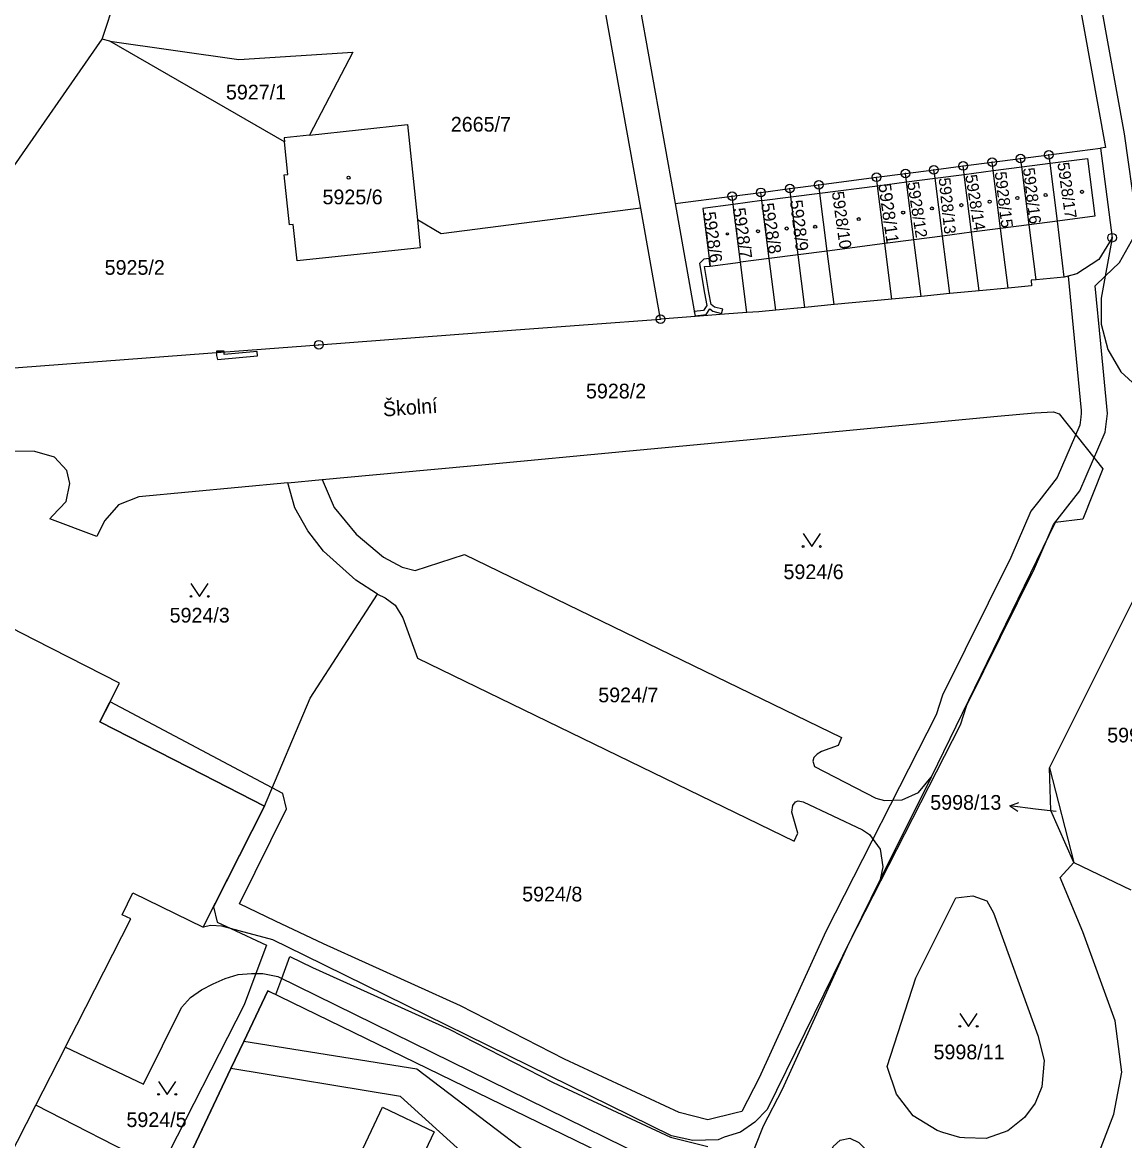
# Model space of a CAD drawing. Extents: x -644096 to -634268, y -1141430 to -1133463.
# Drawn here: x -639819.5 to -639692.1, y -1138952.5 to -1138823.3 of the extents above; entities that cross this region are included whole.
import ezdxf

# ---------------------------------------------------------------- set-up
doc = ezdxf.new("R2010")
doc.units = 0
for name, color, linetype in [('_CIVIL_CONSTRUCTION', 7, 'Continuous'), ('B_Hranice _3D', 7, 'Continuous'), ('M_Svah_Nasyp', 7, 'Continuous'), ('M_Svah_Zarez', 7, 'Continuous'), ('svrsek_osa_sjezdy', 7, 'Continuous'), ('svrsek_osa_terminal_VRT', 7, 'Continuous'), ('svrsek_osa_VRT', 7, 'Continuous'), ('svrsek_popisy_VRT', 7, 'Continuous'), ('terminal_VRT', 7, 'Continuous')]:
    doc.layers.add(name, color=color, linetype=linetype)

msp = doc.modelspace()

# ---------------------------------------------------------------- linework, layer by layer
at = {"layer": '_CIVIL_CONSTRUCTION'}
for centre, radius in [((-639700.83, -1138838.58), 0.5), ((-639710.73, -1138839.87), 0.5), ((-639707.38, -1138839.43), 0.5), ((-639707.38, -1138839.43), 0.0303), ((-639704.1, -1138839), 0.5), ((-639704.1, -1138839), 0.0303), ((-639700.83, -1138838.58), 0.0303), ((-639720.76, -1138841.18), 0.5), ((-639717.4, -1138840.74), 0.5), ((-639717.4, -1138840.74), 0.0303), ((-639714.11, -1138840.31), 0.5), ((-639714.11, -1138840.31), 0.0303), ((-639710.73, -1138839.87), 0.0303), ((-639730.78, -1138842.48), 0.5), ((-639727.41, -1138842.04), 0.5), ((-639727.41, -1138842.04), 0.0303), ((-639720.76, -1138841.18), 0.0303), ((-639737.44, -1138843.35), 0.5), ((-639737.44, -1138843.35), 0.0303), ((-639734.13, -1138842.92), 0.5), ((-639734.13, -1138842.92), 0.0303), ((-639730.78, -1138842.48), 0.0303), ((-639693.53, -1138848.16), 0.5), ((-639693.53, -1138848.16), 0.0303), ((-639745.7, -1138857.57), 0.5), ((-639745.7, -1138857.57), 0.0303), ((-639785.19, -1138860.53), 0.5), ((-639785.19, -1138860.53), 0.0303)]:
    msp.add_circle(centre, radius, dxfattribs=at)
at = {"layer": 'B_Hranice _3D'}
for points in [[(-639710.19, -1138704.51), (-639707.75, -1138718.55), (-639706.98, -1138722.49), (-639707.1, -1138723), (-639703.72, -1138740.51), (-639711.6, -1138742.31), (-639704.99, -1138778.75), (-639703.51, -1138786.84), (-639694.29, -1138837.72), (-639694.86, -1138837.8), (-639693.53, -1138848.16), (-639695.07, -1138850.69), (-639697.61, -1138852.33), (-639698.6, -1138852.6), (-639697.11, -1138868.12)], [(-639737.91, -1138961.12), (-639733.8, -1138950.84), (-639731.61, -1138946.6), (-639723.9, -1138929.67), (-639711.06, -1138904.49), (-639710.31, -1138902.21), (-639702.5, -1138886.39), (-639700.31, -1138881.33), (-639697.27, -1138877.43), (-639694.34, -1138870.64), (-639694.06, -1138868.48), (-639694.83, -1138860.43), (-639695.48, -1138853.71), (-639694.32, -1138852.6), (-639692.67, -1138851.01), (-639690.94, -1138847.96), (-639690.76, -1138845.7), (-639692.1, -1138836.17), (-639698.53, -1138800.59)], [(-639697.11, -1138868.12), (-639697.08, -1138868.44), (-639697.14, -1138868.91), (-639697.26, -1138869.84), (-639699.87, -1138875.89), (-639702, -1138878.63), (-639702.91, -1138879.79), (-639705.23, -1138885.13), (-639713.12, -1138901.05), (-639713.84, -1138903.33), (-639726.6, -1138928.37), (-639734.31, -1138945.28), (-639736.32, -1138949.18), (-639736.97, -1138949.34), (-639740.23, -1138950.14), (-639743.57, -1138949.3), (-639756.81, -1138943.14), (-639768.83, -1138936.97), (-639784.68, -1138929.79), (-639790.2, -1138927.17), (-639794.36, -1138925.18), (-639788.95, -1138914.19), (-639789.37, -1138912.41), (-639809.33, -1138901.81), (-639810.5, -1138904.13), (-639798.6, -1138910.23), (-639791.48, -1138913.88), (-639797.39, -1138925.51), (-639796.96, -1138927.29), (-639795.38, -1138928.02), (-639791.24, -1138929.93), (-639792.48, -1138933.22), (-639793.84, -1138936.84), (-639803.5, -1138955.81)], [(-639801.37, -1138956.9), (-639795.36, -1138944.2), (-639793.88, -1138941.09), (-639791.09, -1138935.21), (-639790.19, -1138935.65), (-639789.49, -1138933.8), (-639788.54, -1138931.27), (-639785.95, -1138932.51), (-639770.15, -1138939.67), (-639758.13, -1138945.84), (-639744.57, -1138952.14), (-639740.25, -1138953.22)]]:
    msp.add_lwpolyline(points, dxfattribs=at)
for points in [[(-639741.72, -1138857.2), (-639740.45, -1138857.04), (-639740.02, -1138856.4), (-639739.68, -1138856.67), (-639738.65, -1138856.92), (-639738.53, -1138856.44), (-639739.46, -1138856.21), (-639739.85, -1138855.9), (-639740.14, -1138854.49), (-639740.62, -1138851.51), (-639739.97, -1138851.46), (-639740.08, -1138850.56), (-639740.69, -1138850.63), (-639741.19, -1138851.14), (-639740.64, -1138854.59), (-639740.35, -1138855.99), (-639740.73, -1138856.58), (-639741.81, -1138856.71)], [(-639797.02, -1138861.27), (-639797.02, -1138861.42), (-639796.14, -1138861.36), (-639796.14, -1138861.27)], [(-639797.02, -1138861.42), (-639797.02, -1138861.77), (-639796.91, -1138862.23), (-639792.29, -1138861.83), (-639792.33, -1138861.33), (-639796.14, -1138861.67), (-639796.14, -1138861.36)]]:
    msp.add_lwpolyline(points, close=True, dxfattribs=at)
at = {"layer": 'M_Svah_Nasyp'}
for p, q in [((-639700.7, -1138839.55), (-639696.38, -1138838.99)), ((-639696.38, -1138838.99), (-639695.52, -1138845.68)), ((-639710.61, -1138840.84), (-639707.26, -1138840.41)), ((-639707.26, -1138840.41), (-639703.97, -1138839.98)), ((-639703.97, -1138839.98), (-639700.7, -1138839.55)), ((-639720.64, -1138842.15), (-639717.28, -1138841.71)), ((-639717.28, -1138841.71), (-639713.99, -1138841.28)), ((-639713.99, -1138841.28), (-639710.61, -1138840.84)), ((-639730.66, -1138843.45), (-639727.29, -1138843.01)), ((-639727.29, -1138843.01), (-639720.64, -1138842.15)), ((-639737.32, -1138844.31), (-639740.82, -1138844.77)), ((-639734.01, -1138843.88), (-639737.32, -1138844.31)), ((-639734.01, -1138843.88), (-639730.66, -1138843.45)), ((-639740.82, -1138844.77), (-639739.97, -1138851.46)), ((-639695.52, -1138845.68), (-639699.84, -1138846.24)), ((-639706.41, -1138847.1), (-639709.76, -1138847.53)), ((-639703.11, -1138846.67), (-639706.41, -1138847.1)), ((-639699.84, -1138846.24), (-639703.11, -1138846.67)), ((-639716.43, -1138848.4), (-639719.79, -1138848.84)), ((-639713.14, -1138847.97), (-639716.43, -1138848.4)), ((-639709.76, -1138847.53), (-639713.14, -1138847.97)), ((-639726.44, -1138849.7), (-639729.81, -1138850.14)), ((-639719.79, -1138848.84), (-639726.44, -1138849.7)), ((-639739.97, -1138851.46), (-639736.47, -1138851)), ((-639733.16, -1138850.57), (-639736.47, -1138851)), ((-639729.81, -1138850.14), (-639733.16, -1138850.57))]:
    msp.add_line(p, q, dxfattribs=at)
at = {"layer": 'M_Svah_Zarez'}
for centre, radius in [((-639781.77, -1138841.23), 0.175), ((-639701.21, -1138843.23), 0.175), ((-639697, -1138842.86), 0.175), ((-639714.35, -1138844.78), 0.175), ((-639710.94, -1138844.4), 0.175), ((-639707.68, -1138844), 0.175), ((-639704.47, -1138843.57), 0.175), ((-639722.8, -1138846.01), 0.175), ((-639717.67, -1138845.26), 0.175), ((-639734.45, -1138847.41), 0.175), ((-639731.13, -1138847.1), 0.175), ((-639727.84, -1138846.9), 0.175), ((-639737.99, -1138847.73), 0.117)]:
    msp.add_circle(centre, radius, dxfattribs=at)
at = {"layer": 'svrsek_osa_sjezdy'}
for points in [[(-639729.24, -1138882.36), (-639728.24, -1138883.86), (-639727.24, -1138882.36)], [(-639799.98, -1138888.13), (-639798.98, -1138889.63), (-639797.98, -1138888.13)], [(-639711.12, -1138937.83), (-639710.12, -1138939.33), (-639709.12, -1138937.83)], [(-639803.73, -1138945.69), (-639802.73, -1138947.19), (-639801.73, -1138945.69)]]:
    msp.add_lwpolyline(points, dxfattribs=at)
for centre in [(-639729.24, -1138883.86), (-639727.24, -1138883.86), (-639799.98, -1138889.63), (-639797.98, -1138889.63), (-639711.12, -1138939.33), (-639709.12, -1138939.33), (-639803.73, -1138947.19), (-639801.73, -1138947.19)]:
    msp.add_circle(centre, 0.1, dxfattribs=at)
at = {"layer": 'svrsek_osa_terminal_VRT'}
msp.add_arc((-642050.26, -1145189.6), 8802.25, 41.413152, 75.317049, dxfattribs=at)
at = {"layer": 'svrsek_popisy_VRT'}
for p, q in [((-639705.35, -1138913.84), (-639704.29, -1138913.47)), ((-639702.37, -1138914.21), (-639705.35, -1138913.84)), ((-639705.35, -1138913.84), (-639704.42, -1138914.46)), ((-639699.97, -1138914.49), (-639702.37, -1138914.21))]:
    msp.add_line(p, q, dxfattribs=at)
at = {"layer": 'terminal_VRT'}
for p, q in [((-639753.15, -1138793.2), (-639744.04, -1138844.21)), ((-639810.25, -1138825.23), (-639808.3, -1138819.29)), ((-639821.39, -1138841.23), (-639810.25, -1138825.23)), ((-639809.36, -1138825.44), (-639810.25, -1138825.23)), ((-639789.17, -1138837.08), (-639809.36, -1138825.44)), ((-639700.83, -1138838.58), (-639694.86, -1138837.8)), ((-639694.86, -1138837.8), (-639693.53, -1138848.16)), ((-639710.73, -1138839.87), (-639707.38, -1138839.43)), ((-639707.38, -1138839.43), (-639704.1, -1138839)), ((-639704.1, -1138839), (-639700.83, -1138838.58)), ((-639720.76, -1138841.18), (-639717.4, -1138840.74)), ((-639717.4, -1138840.74), (-639714.11, -1138840.31)), ((-639714.11, -1138840.31), (-639710.73, -1138839.87)), ((-639730.78, -1138842.48), (-639727.41, -1138842.04)), ((-639727.41, -1138842.04), (-639720.76, -1138841.18)), ((-639744.04, -1138844.21), (-639737.44, -1138843.35)), ((-639737.44, -1138843.35), (-639734.13, -1138842.92)), ((-639734.13, -1138842.92), (-639730.78, -1138842.48)), ((-639744.04, -1138844.21), (-639741.71, -1138857.27)), ((-639745.7, -1138857.57), (-639748, -1138844.73)), ((-639699.05, -1138852.72), (-639702.29, -1138853.02)), ((-639715.6, -1138854.95), (-639718.97, -1138855.27)), ((-639712.29, -1138854.63), (-639715.6, -1138854.95)), ((-639708.9, -1138854.31), (-639712.29, -1138854.63)), ((-639705.53, -1138853.99), (-639708.9, -1138854.31)), ((-639729.04, -1138856.22), (-639732.4, -1138856.54)), ((-639725.65, -1138855.9), (-639729.04, -1138856.22)), ((-639718.97, -1138855.27), (-639725.65, -1138855.9)), ((-639741.71, -1138857.27), (-639745.7, -1138857.57)), ((-639788.77, -1138876.5), (-639784.81, -1138876.13)), ((-639714.43, -1138910.53), (-639720.34, -1138922.37)), ((-639700.74, -1138909.46), (-639697.94, -1138920.38)), ((-639798.59, -1138927.88), (-639791.48, -1138913.88)), ((-639697.94, -1138920.38), (-639691.37, -1138923.56)), ((-639793.88, -1138941.09), (-639795.36, -1138944.2)), ((-639817.92, -1138948.43), (-639814.49, -1138941.73)), ((-639795.36, -1138944.2), (-639801.37, -1138956.9)), ((-639801.37, -1138956.9), (-639817.92, -1138948.43))]:
    msp.add_line(p, q, dxfattribs=at)
for points in [[(-639704.99, -1138778.75), (-639703.51, -1138786.84), (-639694.29, -1138837.72), (-639694.86, -1138837.8)], [(-639748, -1138844.73), (-639752.48, -1138819.72), (-639755.46, -1138819.2)], [(-639809.36, -1138825.44), (-639794.44, -1138827.58), (-639781.26, -1138826.73), (-639786.27, -1138836.3)], [(-639786.27, -1138836.3), (-639774.96, -1138835.07), (-639773.81, -1138846.1)], [(-639786.27, -1138836.3), (-639789.22, -1138836.62), (-639789.17, -1138837.08)], [(-639773.81, -1138846.1), (-639773.48, -1138849.32), (-639787.72, -1138850.83), (-639788.18, -1138846.63), (-639788.6, -1138846.66), (-639789.21, -1138840.89), (-639788.77, -1138840.87), (-639789.17, -1138837.08)], [(-639705.53, -1138853.99), (-639706.41, -1138847.1), (-639707.26, -1138840.41), (-639707.38, -1138839.43)], [(-639702.29, -1138853.02), (-639703.11, -1138846.67), (-639703.97, -1138839.98), (-639704.1, -1138839)], [(-639699.05, -1138852.72), (-639699.84, -1138846.24), (-639700.7, -1138839.55), (-639700.83, -1138838.58)], [(-639715.6, -1138854.95), (-639716.43, -1138848.4), (-639717.28, -1138841.71), (-639717.4, -1138840.74)], [(-639712.29, -1138854.63), (-639713.14, -1138847.97), (-639713.99, -1138841.28), (-639714.11, -1138840.31)], [(-639708.9, -1138854.31), (-639709.76, -1138847.53), (-639710.61, -1138840.84), (-639710.73, -1138839.87)], [(-639725.65, -1138855.9), (-639726.44, -1138849.7), (-639727.29, -1138843.01), (-639727.41, -1138842.04)], [(-639718.97, -1138855.27), (-639719.79, -1138848.84), (-639720.64, -1138842.15), (-639720.76, -1138841.18)], [(-639735.73, -1138856.82), (-639736.47, -1138851), (-639737.32, -1138844.31), (-639737.44, -1138843.35)], [(-639732.4, -1138856.54), (-639733.16, -1138850.57), (-639734.01, -1138843.88), (-639734.13, -1138842.92)], [(-639729.04, -1138856.22), (-639729.81, -1138850.14), (-639730.66, -1138843.45), (-639730.78, -1138842.48)], [(-639748, -1138844.73), (-639771.05, -1138847.73), (-639773.81, -1138846.1)], [(-639693.53, -1138848.16), (-639695.07, -1138850.69), (-639697.61, -1138852.33), (-639699.05, -1138852.72)], [(-639693.53, -1138848.16), (-639694.78, -1138855.15), (-639694.78, -1138858.15), (-639694.01, -1138861.08), (-639692.5, -1138863.66), (-639690.28, -1138865.7), (-639687.62, -1138867.07), (-639684.68, -1138867.7), (-639681.02, -1138869.43)], [(-639702.29, -1138853.02), (-639702.89, -1138853.07), (-639702.84, -1138853.74), (-639705.53, -1138853.99)], [(-639834.99, -1138864.29), (-639829.63, -1138863.88), (-639798.02, -1138861.5), (-639785.19, -1138860.53), (-639762.44, -1138858.82), (-639745.7, -1138857.57)], [(-639735.73, -1138856.82), (-639738.33, -1138857.02), (-639741.71, -1138857.27)], [(-639732.4, -1138856.54), (-639734.35, -1138856.72), (-639735.73, -1138856.82)], [(-639791.48, -1138913.88), (-639798.6, -1138910.23), (-639810.5, -1138904.13), (-639808.24, -1138899.66), (-639817.99, -1138894.67), (-639830.53, -1138888.24), (-639828.47, -1138884.15), (-639844.57, -1138875.91), (-639846.71, -1138874.81), (-639855.72, -1138870.2), (-639867.76, -1138864.04), (-639870.37, -1138869.15), (-639879.31, -1138886.65), (-639867.97, -1138892.45), (-639869.12, -1138894.87), (-639869.95, -1138894.51), (-639876.7, -1138907.72)], [(-639784.81, -1138876.13), (-639772.67, -1138874.99), (-639766.35, -1138874.42), (-639749.3, -1138872.8), (-639725.05, -1138870.51), (-639706.75, -1138868.79), (-639702.44, -1138868.39), (-639700.31, -1138868.28), (-639699.64, -1138868.52), (-639694.58, -1138874.88), (-639696.92, -1138880.7), (-639700.12, -1138881.1), (-639714.43, -1138910.53)], [(-639700.74, -1138909.46), (-639690.01, -1138887.93), (-639681.02, -1138869.43)], [(-639788.77, -1138876.5), (-639806, -1138878.11), (-639808.37, -1138879.03), (-639809.93, -1138880.85), (-639810.81, -1138882.58), (-639810.88, -1138882.71), (-639816.28, -1138880.67), (-639815.97, -1138880.33), (-639814.39, -1138878.64), (-639814, -1138876.56), (-639814.33, -1138875.08), (-639815.75, -1138873.54), (-639818.02, -1138872.89), (-639823, -1138872.81)], [(-639778.43, -1138889.36), (-639780.94, -1138887.75), (-639784.66, -1138884.39), (-639786.47, -1138882.05), (-639787.96, -1138879.4), (-639788.77, -1138876.5)], [(-639784.81, -1138876.13), (-639783.42, -1138879.37), (-639780.88, -1138882.44), (-639777.73, -1138885.08), (-639775.56, -1138886.24), (-639774.09, -1138886.65), (-639768.35, -1138884.8), (-639724.79, -1138905.95), (-639725.18, -1138906.85), (-639727.11, -1138907.57), (-639727.6, -1138907.86), (-639728.01, -1138908.27), (-639728.1, -1138908.69), (-639727.92, -1138909.3), (-639720.83, -1138912.94), (-639719.82, -1138913.22), (-639717.8, -1138913.13), (-639715.9, -1138912.28), (-639714.43, -1138910.53)], [(-639791.48, -1138913.88), (-639786.22, -1138901.38), (-639778.43, -1138889.36)], [(-639778.43, -1138889.36), (-639777.54, -1138889.78), (-639776.38, -1138890.65), (-639775.51, -1138892.09), (-639773.82, -1138896.76), (-639730.27, -1138917.93), (-639729.83, -1138916.98), (-639730.54, -1138914.58), (-639730.43, -1138913.8), (-639730.12, -1138913.37), (-639729.8, -1138913.27), (-639729.24, -1138913.37), (-639722.38, -1138916.61), (-639721.58, -1138917.15), (-639720.34, -1138918.86), (-639720.01, -1138920.89), (-639720.34, -1138922.37)], [(-639876.7, -1138907.72), (-639889.47, -1138932.72), (-639887.99, -1138933.47), (-639889.35, -1138936.22), (-639880.44, -1138940.76), (-639879.23, -1138938.38), (-639872.49, -1138941.81), (-639864.68, -1138926.52), (-639858.4, -1138914.21), (-639853.21, -1138904.06), (-639832.07, -1138914.84), (-639824.43, -1138918.74), (-639829.88, -1138929.45), (-639843.67, -1138956.54), (-639836.98, -1138959.94), (-639838.22, -1138962.36), (-639829.23, -1138966.94), (-639827.84, -1138964.19), (-639826.37, -1138964.95), (-639825.4, -1138963.05), (-639817.92, -1138948.43)], [(-639697.94, -1138920.38), (-639700.59, -1138914.38), (-639700.74, -1138909.46)], [(-639701.19, -1138984), (-639700.61, -1138972.63), (-639700.39, -1138970.13), (-639699.57, -1138967.19), (-639696.16, -1138956.91), (-639693.31, -1138949.48), (-639692.38, -1138944.61), (-639693.17, -1138938.71), (-639696.92, -1138928.42), (-639699.52, -1138922.11), (-639697.94, -1138920.38)], [(-639720.34, -1138922.37), (-639733.39, -1138948.95), (-639734.8, -1138950.41), (-639736.46, -1138951.56), (-639738.35, -1138952.15), (-639739.07, -1138952.43), (-639741.99, -1138952.52), (-639744.44, -1138951.99), (-639786.9, -1138931.09), (-639790.51, -1138929.34), (-639794.4, -1138928.27), (-639796.43, -1138927.75), (-639797.68, -1138927.68), (-639798.59, -1138927.88)], [(-639814.49, -1138941.73), (-639814.39, -1138941.53), (-639813.17, -1138939.15), (-639806.92, -1138926.92), (-639807.93, -1138926.43), (-639806.69, -1138923.91), (-639798.59, -1138927.88)], [(-639702.43, -1138948.21), (-639703.63, -1138949.88), (-639705.57, -1138951.42), (-639708.06, -1138952.31), (-639710.6, -1138952.23), (-639711.13, -1138952.19), (-639713.07, -1138951.62), (-639713.74, -1138951.38), (-639716.5, -1138949.66), (-639718.45, -1138947.16), (-639719.51, -1138943.97), (-639716.19, -1138933.72), (-639711.58, -1138924.46), (-639709.6, -1138924.23), (-639708, -1138924.81), (-639707.23, -1138926.19), (-639702.09, -1138940.37), (-639701.37, -1138943.29), (-639701.65, -1138946.33), (-639702.43, -1138948.21)], [(-639814.49, -1138941.73), (-639805.48, -1138946.03), (-639801.06, -1138937.15), (-639800.05, -1138935.99), (-639798.77, -1138935.09), (-639797.43, -1138934.41), (-639796.03, -1138933.78), (-639794.53, -1138933.33), (-639793, -1138933.22), (-639791.68, -1138933.22), (-639789.95, -1138933.58), (-639741.03, -1138957.6), (-639745.81, -1138967.32)], [(-639749.83, -1138955.29), (-639791.09, -1138935.21), (-639793.88, -1138941.09)], [(-639752.8, -1138960.29), (-639773.88, -1138944.28), (-639793.88, -1138941.09)], [(-639756.08, -1138965.29), (-639775.77, -1138947.43), (-639795.36, -1138944.2)], [(-639777.83, -1138948.69), (-639771.89, -1138951.54), (-639775.42, -1138959), (-639781.39, -1138956.18), (-639777.83, -1138948.69)], [(-639737.56, -1138977.45), (-639732.26, -1138966.6), (-639725.75, -1138953.23), (-639724.96, -1138952.49), (-639723.82, -1138952.27), (-639722.78, -1138952.74), (-639720.87, -1138954.64), (-639717.88, -1138956.9), (-639713.58, -1138958.76), (-639712.85, -1138961.03), (-639709.36, -1138962.85), (-639706.7, -1138964.93), (-639705.32, -1138966.65), (-639704.49, -1138968.36), (-639704.05, -1138970.58), (-639704.79, -1138985.02)]]:
    msp.add_lwpolyline(points, dxfattribs=at)

# ---------------------------------------------------------------- texts
at = {"layer": 'svrsek_osa_VRT'}
for s, p in [('5927/1', (-639795.94, -1138832.18)), ('2665/7', (-639769.95, -1138835.9)), ('5925/6', (-639784.78, -1138844.3)), ('5925/2', (-639809.96, -1138852.45)), ('5928/2', (-639754.33, -1138866.74)), ('5924/6', (-639731.5, -1138887.63)), ('5924/3', (-639802.45, -1138892.65)), ('5924/7', (-639752.91, -1138901.87)), ('5996/1', (-639694.09, -1138906.51)), ('5998/13', (-639714.54, -1138914.29)), ('5924/8', (-639761.7, -1138924.89)), ('5998/11', (-639714.16, -1138943.14)), ('5924/5', (-639807.44, -1138950.97))]:
    msp.add_text(s, height=1.7, dxfattribs=at).set_placement(p)
for s, height, rotation, p in [('5928/15', 1.354, 277, (-639707.1, -1138840.6)), ('5928/16', 1.354, 277, (-639703.84, -1138840.15)), ('5928/17', 1.354, 278, (-639699.85, -1138839.54)), ('5928/11', 1.452, 278, (-639720.55, -1138841.98)), ('5928/12', 1.354, 279, (-639717.21, -1138841.8)), ('5928/13', 1.354, 276, (-639713.58, -1138841.29)), ('5928/14', 1.354, 279, (-639710.5, -1138840.97)), ('5928/10', 1.386, 278, (-639725.92, -1138842.9)), ('5928/8', 1.452, 279, (-639734.09, -1138844.26)), ('5928/9', 1.452, 277, (-639730.77, -1138843.88)), ('5928/6', 1.452, 278, (-639740.81, -1138845.26)), ('5928/7', 1.452, 278, (-639737.37, -1138844.8))]:
    msp.add_text(s, height=height, rotation=rotation, dxfattribs=at).set_placement(p)
at = {"layer": 'svrsek_popisy_VRT'}
msp.add_text('Školní', height=1.7, rotation=4, dxfattribs=at).set_placement((-639777.74, -1138868.84))

doc.saveas('drawing.dxf')
